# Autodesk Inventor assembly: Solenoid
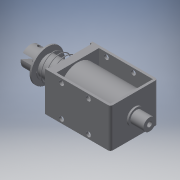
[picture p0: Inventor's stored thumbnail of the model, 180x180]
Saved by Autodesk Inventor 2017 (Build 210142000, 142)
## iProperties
Created: 2017-01
Part Number: Solenoid
Document SubType Name: Assembly
Designer: yul067
Author: yul067
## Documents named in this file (5)
- C:\Users\yul067\Desktop\ECE 115 solenoid\Solenoid.iam
- C:\Users\yul067\Desktop\ECE 115 solenoid\body.ipt
- C:\Users\yul067\Desktop\ECE 115 solenoid\cylinder.ipt
- C:\Users\yul067\Desktop\ECE 115 solenoid\shaft.ipt
- C:\Users\yul067\Desktop\ECE 115 solenoid\spring.ipt
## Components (4 placed, 4 different names)
1. body:1 — Rigid:1, Cylindrical:1, Mate:1
2. cylinder:1 — Rigid:1
3. shaft:1 — Cylindrical:1
4. Spring:1 — Mate:1
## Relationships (3: WeldJoint 1, CylindricalJoint 1, Mate 1)
- Rigid:1 [WeldJoint]: body:1 ↔ cylinder:1
- Cylindrical:1: body:1 ↔ shaft:1
- Mate:1: body:1 ↔ Spring:1
